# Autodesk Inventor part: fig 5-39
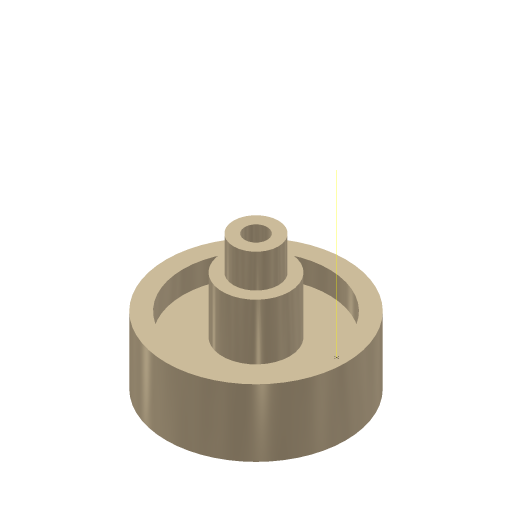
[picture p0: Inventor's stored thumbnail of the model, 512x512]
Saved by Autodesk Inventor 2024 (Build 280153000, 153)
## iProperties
Created: 2001-11
Part Number: fig 5-39
Document SubType Name: Modeling
Designer: Renu Muthoo
Density: 1 g/cm^3
Material: Generic
Appearance: Metal-Titanium (Polished)
Control State: 0
Master: False
Checked Out: False
Shininess: 65.0
Length Units: 11269
Angle Units: 11279
Time Units: 11290
Mass Units: 11283
Length Display Precision: 3
Angle Display Precision: 2
Density: 0.0
Volumn: 0.0
Area: 0.0
PropertySet Name: Model Information
Author: Renu Muthoo
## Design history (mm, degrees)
sketch "Sketch1"
  geometry: L1 (2.694, 30.112)-(5.194, 30.112); L2 (5.194, 30.112)-(5.194, 22.612); L3 (5.194, 22.612)-(7.694, 22.612); L4 (7.694, 22.612)-(7.694, 10.112); L5 (7.694, 10.112)-(16.444, 10.112); L6 (16.444, 10.112)-(16.444, 15.112); L7 (16.444, 15.112)-(20.194, 15.112); L8 (0.194, -4.034)-(0.194, 25.966); L9 (2.694, 30.112)-(2.694, 0.112); L10 (2.694, 0.112)-(20.194, 0.112); L11 (20.194, 0.112)-(20.194, 15.112)
  constraints: 22 end point, 7 parallel, 2 perpendicular, 1 horizontal
  dimensions: "d0" = 5 diameter of L9 L8; "d1" = 10 diameter of L2 L8; "d2" = 15 diameter of L4 L8; "d3" = 32.5 diameter of L6 L8; "d4" = 40 diameter of L11 L8; "d5" = 15 distance of L10.end L7.end; "d6" = 22.5 distance between parallel lines of L3 L10; "d7" = 30 distance between parallel lines of L1 L10; "d8" = 10 distance between parallel lines of L10 L5
revolve "Revolution1" sketch "Sketch1" stored, may be unused: angle "d9" = 90 deg
workaxis "Work Axis1"
sketch "Sketch2"
  geometry: 1 further point
workaxis "Work Axis3"
body "Solid1"
node "Sketch3"
